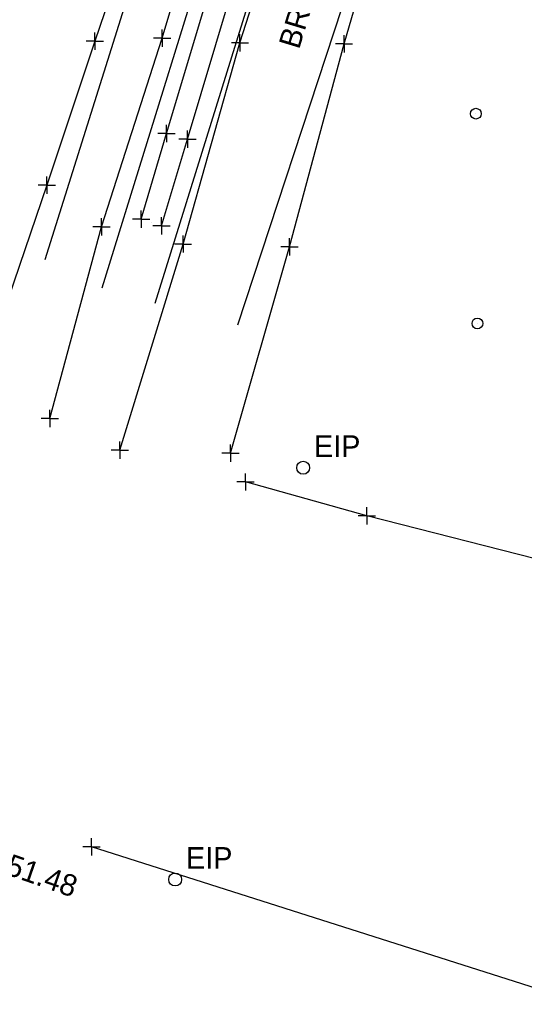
# Model space of a CAD drawing. Extents: x 0 to 1944463, y 0 to 420651.
# Drawn here: x 1943065.6 to 1943182.7, y 417108.3 to 417335.4 of the extents above; entities that cross this region are included whole.
import ezdxf

# ---------------------------------------------------------------- set-up
doc = ezdxf.new("R2010")
doc.units = 0
for name, color, linetype in [('Default', 7, 'Continuous'), ('SUR - DRG - Storm Sewer', 7, 'Continuous'), ('SUR - DRG - Storm Sewer - Points - Locators', 7, 'Continuous'), ('SUR - DRG - Storm Sewer Text', 7, 'Continuous'), ('SUR - DTM - Breaklines', 7, 'Continuous'), ('SUR - DTM - Breaklines - Points - Locators', 7, 'Continuous'), ('SUR - DTM - Spot Points - Locators', 7, 'Continuous'), ('SUR - NON-TRAN - Features', 7, 'Continuous'), ('SUR - NON-TRAN - Features - Points - Locators', 7, 'Continuous'), ('SUR - PROPERTY - Property Markers', 7, 'Continuous'), ('SUR - TRAN - Railroads', 7, 'Continuous'), ('SUR - TRAN - Railroads - Points - Locators', 7, 'Continuous'), ('SUR - VEG - Features', 7, 'Continuous'), ('SUR - VEG - Features Text', 7, 'Continuous')]:
    doc.layers.add(name, color=color, linetype=linetype)

msp = doc.modelspace()

# ---------------------------------------------------------------- linework, layer by layer
at = {"layer": 'Default'}
msp.add_line((1943096.16, 417288.33), (1943096.16, 417288.33), dxfattribs=at)
at = {"layer": 'SUR - DRG - Storm Sewer'}
msp.add_lwpolyline([(1943301.03, 417074.1), (1943082.28, 417143.65)], dxfattribs=at)
at = {"layer": 'SUR - DRG - Storm Sewer - Points - Locators'}
for q in [(1943082.28, 417145.65), (1943080.28, 417143.65), (1943084.28, 417143.65), (1943082.28, 417141.65)]:
    msp.add_line((1943082.28, 417143.65), q, dxfattribs=at)
at = {"layer": 'SUR - DTM - Breaklines'}
for points in [[(1943133.1, 417474.8), (1943132.17, 417462.89), (1943122.24, 417443.95), (1943114.48, 417423.78), (1943107.47, 417399.09), (1943101.65, 417398.72), (1943096.06, 417383.93), (1943099.01, 417377.11), (1943083.08, 417330.36), (1943071.96, 417297.01), (1943056.58, 417252.03)], [(1943072.65, 417242.91), (1943084.6, 417287.36), (1943098.67, 417331.06), (1943112.05, 417375.67), (1943127.71, 417421.62), (1943141.02, 417463.43)], [(1943088.85, 417235.62), (1943103.52, 417283.36), (1943116.73, 417330), (1943131.72, 417376.66), (1943145.98, 417422.39), (1943153.32, 417445.75)], [(1943114.51, 417234.88), (1943128.23, 417282.69), (1943140.85, 417329.77), (1943154.73, 417377.21), (1943160.7, 417388.38)]]:
    msp.add_lwpolyline(points, dxfattribs=at)
at = {"layer": 'SUR - DTM - Breaklines - Points - Locators'}
for p, q in [((1943083.08, 417330.36), (1943083.08, 417332.36)), ((1943098.67, 417331.06), (1943098.67, 417333.06)), ((1943116.73, 417330), (1943116.73, 417332)), ((1943140.85, 417329.77), (1943140.85, 417331.77)), ((1943083.08, 417330.36), (1943081.08, 417330.36)), ((1943083.08, 417330.36), (1943085.08, 417330.36)), ((1943083.08, 417330.36), (1943083.08, 417328.36)), ((1943098.67, 417331.06), (1943096.67, 417331.06)), ((1943098.67, 417331.06), (1943100.67, 417331.06)), ((1943098.67, 417331.06), (1943098.67, 417329.06)), ((1943116.73, 417330), (1943114.73, 417330)), ((1943116.73, 417330), (1943118.73, 417330)), ((1943116.73, 417330), (1943116.73, 417328)), ((1943140.85, 417329.77), (1943138.85, 417329.77)), ((1943140.85, 417329.77), (1943142.85, 417329.77)), ((1943140.85, 417329.77), (1943140.85, 417327.77)), ((1943071.96, 417297.01), (1943071.96, 417299.01)), ((1943071.96, 417297.01), (1943069.96, 417297.01)), ((1943071.96, 417297.01), (1943073.96, 417297.01)), ((1943071.96, 417297.01), (1943071.96, 417295.01)), ((1943084.6, 417287.36), (1943084.6, 417289.36)), ((1943084.6, 417287.36), (1943082.6, 417287.36)), ((1943084.6, 417287.36), (1943086.6, 417287.36)), ((1943084.6, 417287.36), (1943084.6, 417285.36)), ((1943103.52, 417283.36), (1943103.52, 417285.36)), ((1943128.23, 417282.69), (1943128.23, 417284.69)), ((1943103.52, 417283.36), (1943101.52, 417283.36)), ((1943103.52, 417283.36), (1943105.52, 417283.36)), ((1943103.52, 417283.36), (1943103.52, 417281.36)), ((1943128.23, 417282.69), (1943126.23, 417282.69)), ((1943128.23, 417282.69), (1943130.23, 417282.69)), ((1943128.23, 417282.69), (1943128.23, 417280.69)), ((1943072.65, 417242.91), (1943072.65, 417244.91)), ((1943072.65, 417242.91), (1943070.65, 417242.91)), ((1943072.65, 417242.91), (1943074.65, 417242.91)), ((1943072.65, 417242.91), (1943072.65, 417240.91)), ((1943088.85, 417235.62), (1943088.85, 417237.62)), ((1943114.51, 417234.88), (1943114.51, 417236.88)), ((1943088.85, 417235.62), (1943086.85, 417235.62)), ((1943088.85, 417235.62), (1943090.85, 417235.62)), ((1943088.85, 417235.62), (1943088.85, 417233.62)), ((1943114.51, 417234.88), (1943112.51, 417234.88)), ((1943114.51, 417234.88), (1943116.51, 417234.88)), ((1943114.51, 417234.88), (1943114.51, 417232.88))]:
    msp.add_line(p, q, dxfattribs=at)
at = {"layer": 'SUR - DTM - Spot Points - Locators'}
for p, q in [((1943171.44, 417313.55), (1943171.44, 417313.55)), ((1943171.79, 417264.94), (1943171.79, 417264.94))]:
    msp.add_line(p, q, dxfattribs=at)
for centre in [(1943171.43, 417313.56), (1943171.78, 417264.95)]:
    msp.add_circle(centre, 1.25, dxfattribs=at)
at = {"layer": 'SUR - NON-TRAN - Features'}
msp.add_lwpolyline([(1943308.46, 417173.81), (1943240.68, 417195.55), (1943189.17, 417209.39), (1943146.16, 417220.39), (1943118.02, 417228.22)], dxfattribs=at)
at = {"layer": 'SUR - NON-TRAN - Features - Points - Locators'}
for p, q in [((1943118.02, 417228.22), (1943118.02, 417230.22)), ((1943118.02, 417228.22), (1943116.02, 417228.22)), ((1943118.02, 417228.22), (1943120.02, 417228.22)), ((1943118.02, 417228.22), (1943118.02, 417226.22)), ((1943146.16, 417220.39), (1943146.16, 417222.39)), ((1943146.16, 417220.39), (1943144.16, 417220.39)), ((1943146.16, 417220.39), (1943148.16, 417220.39)), ((1943146.16, 417220.39), (1943146.16, 417218.39))]:
    msp.add_line(p, q, dxfattribs=at)
at = {"layer": 'SUR - PROPERTY - Property Markers'}
for centre in [(1943131.38, 417231.52), (1943101.7, 417136.11)]:
    msp.add_circle(centre, 1.5, dxfattribs=at)
at = {"layer": 'SUR - TRAN - Railroads'}
for points in [[(1943093.8, 417289.09), (1943099.68, 417308.96), (1943109.47, 417341.69), (1943118.91, 417373.09), (1943128.73, 417405.59), (1943143.71, 417455.42), (1943175.9, 417562.25), (1943188.11, 417602.58), (1943216.37, 417696.61), (1943236.5, 417763.05)], [(1943098.53, 417287.57), (1943104.56, 417307.63), (1943114.3, 417340.28), (1943123.75, 417371.73), (1943133.57, 417404.59), (1943148.36, 417453.81), (1943180.54, 417560.57), (1943192.93, 417601.39), (1943221.1, 417695.23), (1943241.09, 417761.6)]]:
    msp.add_lwpolyline(points, dxfattribs=at)
at = {"layer": 'SUR - TRAN - Railroads - Points - Locators'}
for p, q in [((1943099.68, 417308.96), (1943099.68, 417310.96)), ((1943099.68, 417308.96), (1943097.68, 417308.96)), ((1943099.68, 417308.96), (1943101.68, 417308.96)), ((1943099.68, 417308.96), (1943099.68, 417306.96)), ((1943104.56, 417307.63), (1943104.56, 417309.63)), ((1943104.56, 417307.63), (1943102.56, 417307.63)), ((1943104.56, 417307.63), (1943106.56, 417307.63)), ((1943104.56, 417307.63), (1943104.56, 417305.63)), ((1943093.8, 417289.09), (1943093.8, 417291.09)), ((1943093.8, 417289.09), (1943091.8, 417289.09)), ((1943093.8, 417289.09), (1943095.8, 417289.09)), ((1943093.8, 417289.09), (1943093.8, 417287.09)), ((1943098.53, 417287.57), (1943098.53, 417289.57)), ((1943098.53, 417287.57), (1943096.53, 417287.57)), ((1943098.53, 417287.57), (1943100.53, 417287.57)), ((1943098.53, 417287.57), (1943098.53, 417285.57))]:
    msp.add_line(p, q, dxfattribs=at)
at = {"layer": 'SUR - VEG - Features'}
msp.add_line((1943145.15, 417468.33), (1943084.66, 417273.14), dxfattribs=at)
for points in [[(1943071.54, 417279.76), (1943134.33, 417479.35), (1943145.15, 417468.33)], [(1943097.09, 417269.67), (1943155.49, 417457.32), (1943210.45, 417389.88), (1943185.65, 417378.15), (1943164.57, 417411.67), (1943116.14, 417264.55)]]:
    msp.add_lwpolyline(points, dxfattribs=at)

# ---------------------------------------------------------------- texts
at = {"layer": 'SUR - DRG - Storm Sewer Text'}
msp.add_text('INV-1051.48', height=5, rotation=340.7586, dxfattribs=at).set_placement((1943042.46, 417144.27))
at = {"layer": 'SUR - PROPERTY - Property Markers'}
for p in [(1943133.88, 417234.02), (1943104.2, 417138.61)]:
    msp.add_text('EIP', height=5, dxfattribs=at).set_placement(p)
at = {"layer": 'SUR - VEG - Features Text'}
msp.add_text('BRUSH', height=5, rotation=73.1233, dxfattribs=at).set_placement((1943130.42, 417328.29))

doc.saveas('drawing.dxf')
